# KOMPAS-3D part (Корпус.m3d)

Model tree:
1. Эскиз:1
2. Операция выдавливания:1
     Расстояние 1 = 30; Расстояние 2 = 125
3. Эскиз:2
4. Эскиз:3
5. Кинематическая операция:1
     Толщина стенки 1 = 1; Толщина стенки 2 = 1
6. Эскиз:4
7. Операция выдавливания:2
     Расстояние 1 = 5; Расстояние 2 = 5
8. Эскиз:7
9. Операция выдавливания:3
     Расстояние 1 = 15; Расстояние 2 = 15
10. Скругление:1
     Радиус = 20
11. Скругление:2
     Радиус = 30
12. Скругление:3
     Радиус = 50
13. Скругление:4
     Радиус = 60
14. Смещенная плоскость:2
     Расстояние = 140
15. Эскиз:8
16. Операция выдавливания:4
     Расстояние 1 = 32; Расстояние 2 = 15
17. Эскиз:9
18. Вырезать элемент выдавливания:1
     Расстояние 1 = 32
19. Эскиз:10
20. Вырезать элемент выдавливания:2
     Расстояние 1 = 2
21. Эскиз:11
22. Вырезать элемент выдавливания:3
     Расстояние 2 = 40; Расстояние 1 = 2
23. Скругление:5
     Радиус = 3
24. Скругление:6
     Радиус = 1
25. Эскиз:12
26. Вырезать элемент выдавливания:4
     Расстояние 2 = 40; Расстояние 1 = 20
27. Эскиз:13
28. Вырезать элемент выдавливания:5
     Расстояние 2 = 40; Расстояние 1 = 30
